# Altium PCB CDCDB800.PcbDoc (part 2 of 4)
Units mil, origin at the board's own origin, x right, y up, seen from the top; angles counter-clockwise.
Board outline 4100 x 4100 mil, 4 copper layers (Layer 1 - Top Layer, Layer 2 - GND, Layer 3 - PWR, Layer 4 - Bottom Layer), stack 61.2 mil thick; 245 components, 143 nets, 740 pads, 720 vias.
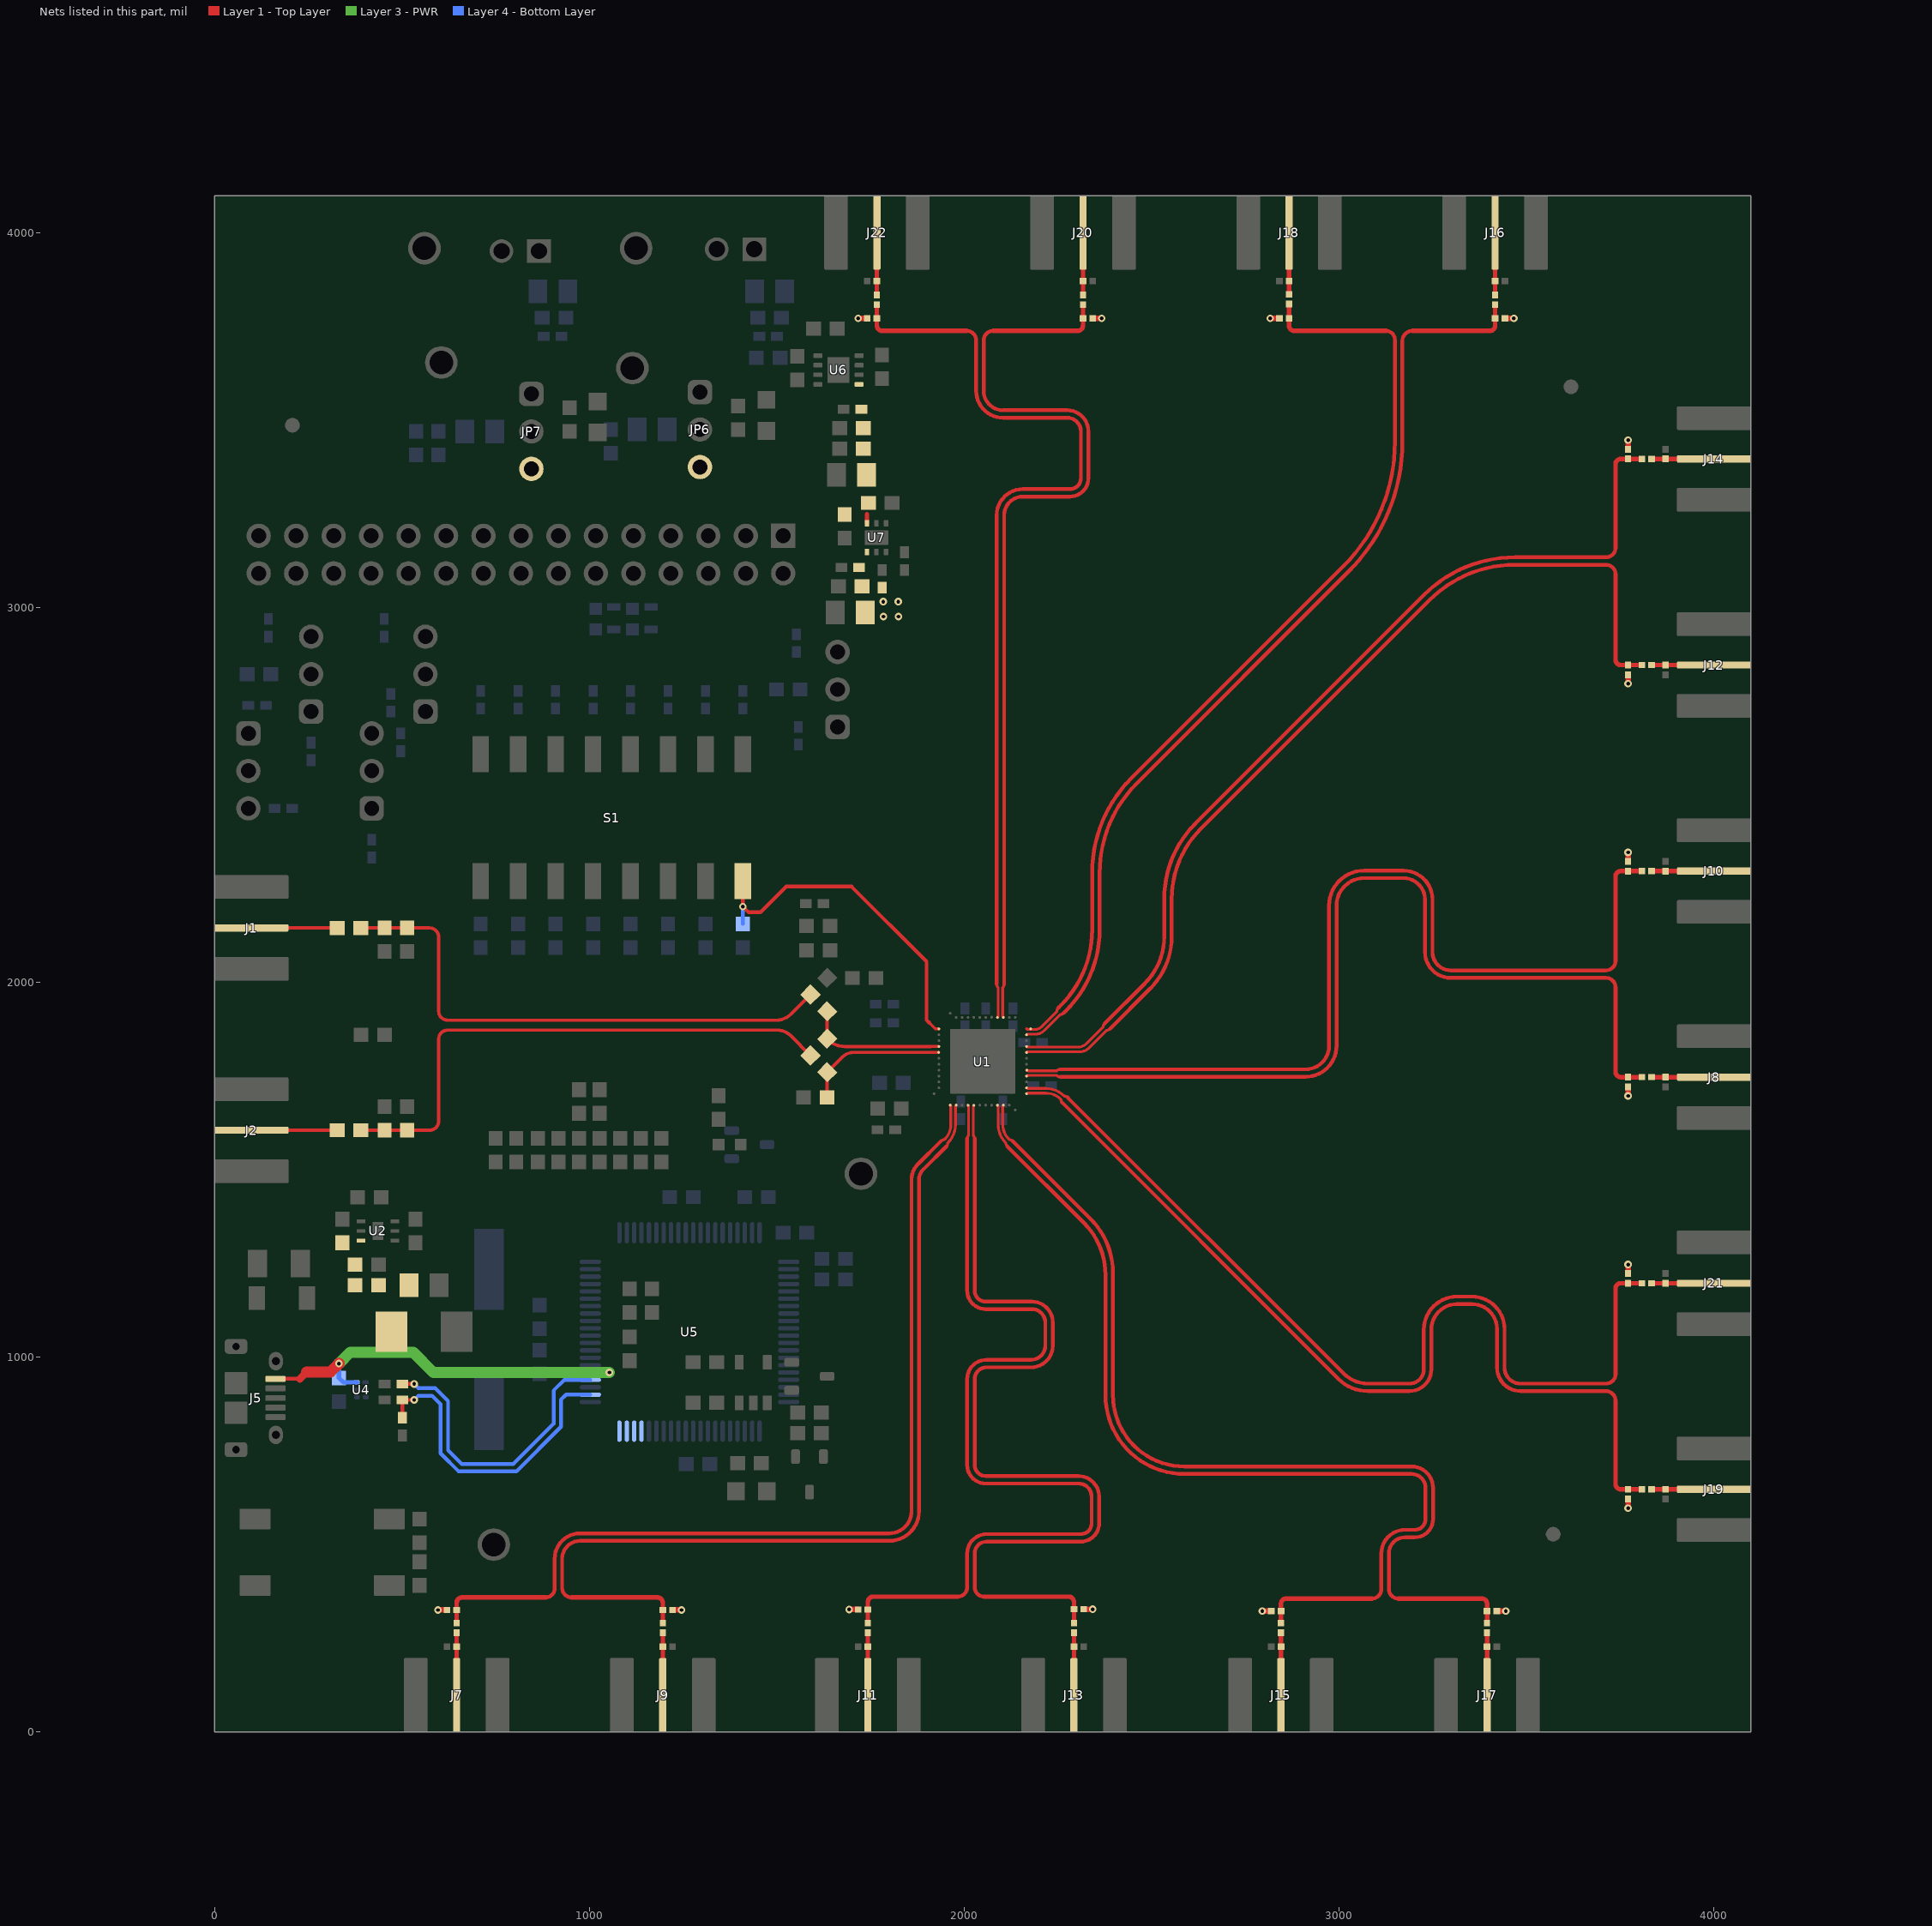
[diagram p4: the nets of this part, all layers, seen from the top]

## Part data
C1 C9 C36 C40 C44 C47: library part CMP-0086062-1, "CAP, CERM, 10 µF, 16 V,+/- 20%, X6S, 0603", Cap_Case=0603, Manufacturer=MuRata, TempCo=X6S, Tolerance_%=20%, Value2=16V, ValueDisplayed=10µF
C2 C3 C4 C5 C6 C7 C8 C10 C11 C12 C15 C37 C41 C45 C48: library part CMP-0006629-2, "CAP, CERM, 0.1 uF, 10 V, +/- 10%, X7R, 0402", Cap_Case=0402, Manufacturer=MuRata, Supplier Part Number 1=GRM155R71A104KA01D-ND, TempCo=X7R, Tolerance_%=10%, Value1=Unknown, Value2=10V, ValueDisplayed=0.1uF
C13 C14: library part CMP-0006722-4, "CAP, CERM, 33 pF, 100 V, +/- 5%, C0G/NP0, 0603", Cap_Case=0603, Manufacturer=AVX, Supplier Part Number 1=478-1143-1-ND, TempCo=C0G/NP0, Tolerance_%=5%, Value1="0.209 ohm", Value2=100V, ValueDisplayed=33pF
C16 C35 C39 C43 C46: library part CMP-0008403-2, "CAP, CERM, 22 uF, 10 V, +/- 20%, X5R, 0805", Cap_Case=0805, Manufacturer="Taiyo Yuden", Supplier Part Number 1=587-1958-1-ND, TempCo=X5R, Tolerance_%=20%, Value1=Unknown, Value2=10V, ValueDisplayed=22uF
C17 C18: library part CMP-0007003-5, "CAP, CERM, 10 uF, 10 V, +/- 20%, X5R, 0603", Cap_Case=0603, Manufacturer=TDK, Supplier Part Number 1=445-6853-1-ND, TempCo=X5R, Tolerance_%=20%, Value1="0.0078 ohm", Value2=10V, ValueDisplayed=10uF
C19 C20 C21 C30 C31 C32: library part CMP-0006857-4, "CAP, CERM, 0.1 uF, 16 V, +/- 5%, X7R, 0603", Cap_Case=0603, Manufacturer=Kemet, Supplier Part Number 1=399-1097-1-ND, TempCo=X7R, Tolerance_%=5%, Value1=Unknown, Value2=16V, ValueDisplayed=0.1uF
C22 C28: library part CMP-0006776-4, "CAP, CERM, 220 pF, 50 V, +/- 1%, C0G/NP0, 0603", Cap_Case=0603, Manufacturer=AVX, Supplier Part Number 1=478-3719-1-ND, TempCo=C0G/NP0, Tolerance_%=1%, Value1="0.083 ohm", Value2=50V, ValueDisplayed=220pF
C23: library part CMP-0006850-4, "CAP, CERM, 0.01 uF, 50 V, +/- 5%, X7R, 0603", Cap_Case=0603, Manufacturer=Kemet, Supplier Part Number 1=399-1092-1-ND, TempCo=X7R, Tolerance_%=5%, Value1=Unknown, Value2=50V, ValueDisplayed=0.01uF
C24: library part CMP-0082522-1, "CAP, CERM, 4.7 µF, 50 V,+/- 10%, X7R, 1206", Cap_Case=1206, Manufacturer=TDK, Supplier Part Number 1=445-172491-1-ND, TempCo=X7R, Tolerance_%=10%, Value2=50V, ValueDisplayed=4.7µF
C25 C26: library part CMP-0007261-4, "CAP, CERM, 30 pF, 100 V, +/- 5%, C0G/NP0, 0603", Cap_Case=0603, Manufacturer=MuRata, Supplier Part Number 1=490-1338-1-ND, TempCo=C0G/NP0, Tolerance_%=5%, Value1=Unknown, Value2=100V, ValueDisplayed=30pF
C27: library part CMP-0006898-4, "CAP, CERM, 2200 pF, 50 V, +/- 10%, X7R, 0603", Cap_Case=0603, Manufacturer=Kemet, Supplier Part Number 1=399-1085-1-ND, TempCo=X7R, Tolerance_%=10%, Value1=Unknown, Value2=50V, ValueDisplayed=2200pF
C29: library part CMP-0007373-4, "CAP, CERM, 0.47 uF, 10 V, +/- 10%, X7R, 0603", Cap_Case=0603, Manufacturer=MuRata, Supplier Part Number 1=GRM188R71A474KA61D-ND, TempCo=X7R, Tolerance_%=10%, Value1=Unknown, Value2=10V, ValueDisplayed=0.47uF
C33 C42: library part CMP-0007067-4, "CAP, CERM, 1 uF, 35 V, +/- 10%, X7R, AEC-Q200 Grade 1, 0603", Cap_Case=0603, Manufacturer=TDK, Supplier Part Number 1=445-174215-1-ND, TempCo=X7R, Tolerance_%=10%, Value1="0.005522 ohm", Value2=35V, ValueDisplayed=1uF
C34: library part CMP-0007497-5, "CAP, CERM, 10 uF, 10 V, +/- 20%, X7R, 0603", Cap_Case=0603, Manufacturer=MuRata, Supplier Part Number 1=81-GRM188Z71A106MA3D, TempCo=X7R, Tolerance_%=20%, Value1=Unknown, Value2=10V, ValueDisplayed=10uF
C38: library part CMP-0006814-5, "CAP, CERM, 0.01 uF, 10 V, +/- 10%, X7R, 0603", Cap_Case=0603, Manufacturer=AVX, Supplier Part Number 1=478-7938-2-ND, TempCo=X7R, Tolerance_%=10%, Value1=Unknown, Value2=10V, ValueDisplayed=0.01uF
D1: library part CMP-0005670-3, "Diode, Zener, 7.5 V, 550 mW, SMB", Manufacturer="ON Semiconductor", Power_W=550mW, Value1=0.55W
D2 D5 D6: library part CMP-0002829-3, "LED, Red, SMD", Color=red, Manufacturer=Lite-On, Value1=W, Value2=2V
D3: library part CMP-0028451-2, "Diode, Schottky, 30 V, 0.2 A, SOT-23", Manufacturer="Diodes Inc.", Value1=0.2A, Value2=0.65V
D4: library part CMP-0002827-3, "LED, Green, SMD", Color=green, Manufacturer=Lite-On, Power_TotalModule=100mW, Value1=0.1W, Value2=2.1V
FID1 FID2 FID3 FID4 FID5 FID6: library part CMP-0077181-1, "Fiducial mark.  There is nothing to buy or mount.", Manufacturer=N/A
H1 H2 H3 H4: library part CMP-0003620-1, "Bumpon, Hemisphere, 0.44 X 0.20, Clear", Manufacturer=3M, Supplier Part Number 1=SJ5303-7-ND
J1 J2 J7 J8 J9 J10 J11 J12 J13 J14 J15 J16 J17 J18 J19 J20 J21 J22: library part CMP-0088000-4, "CONN SMA JACK STR EDGE MNT", Manufacturer="RF Solutions Ltd."
J3 J4: library part CMP-0054974-1, "Terminal Block, 2x1, 2.54mm, TH", Manufacturer="TE Connectivity", Supplier Part Number 1=A98333-ND
J5: library part CMP-0074596-2, "Receptacle, USB 2.0, Micro-USB Type B, R/A, SMT", Color=Black, Current_A=1.8A, Manufacturer=FCI, Supplier Part Number 1=609-4618-1-ND, Voltage_V=100V
J6: library part CMP-0075468-1, "Header, 100mil, 15x2, Gold, TH", Manufacturer=Samtec
JP1 JP2 JP3 JP4 JP5 JP6 JP7: library part CMP-0075407-2, "Header, 100mil, 3x1, Gold, TH", Color=Black, Current_A=6.3A, Manufacturer=Samtec, Supplier Part Number 1=SAM1029-03-ND, Voltage_V=550V
L1 L2: library part CMP-0003081-1, "Ferrite Bead, 330 ohm @ 100 MHz, 2 A, 0805", Manufacturer="Wurth Elektronik", Supplier Part Number 1=732-1619-1-ND, Value1="0.08 ohm", Value2=2A, ValueDisplayed="330 ohm"
L3: library part CMP-0003426-2, "Ferrite Bead, 60 ohm @ 100 MHz, 3.5 A, 0603", Manufacturer=TDK, Supplier Part Number 1=445-1563-1-ND, Value1="0.02 ohm", Value2=3.5A, ValueDisplayed="60 ohm"
Q1: library part CMP-0000281-1, "MOSFET, N-CH, 25 V, 0.22 A, SOT-23", Alternate Manufacturer=None, Manufacturer="Fairchild Semiconductor", Supplier Part Number 1=FDV301NCT-ND, Value2="0.49 nC"
Q2: library part CMP-0000755-1, "MOSFET, N-CH, 50 V, 0.22 A, SOT-23", Alternate Manufacturer=None, Manufacturer="Fairchild Semiconductor", Supplier Part Number 1=BSS138CT-ND, Value2="1.7 nC"
R1: library part CMP-0022711-2, "RES, 2.20, 1%, 0.1 W, 0603", Manufacturer=Panasonic, Power_W=100mW, Supplier Part Number 1=P2.2AJCT-ND, TempCo="200 ppm/C", Tolerance_%=1%, Value2=0.1W, Value_Code=2R20, ValueDisplayed=2.20
R2 R3 R4 R5 R24 R25 R28 R29 R30 R33 R34 R36 R38 R40 R42 R44 R46 R48: library part CMP-0026740-1, "RES, 4.99 k, 1%, 0.063 W, 0402", Manufacturer="Yageo America", Power_W=63mW, Supplier Part Number 1=311-4.99KLRCT-ND, TempCo="100 ppm/C", Tolerance_%=1%, Value2=0.063W, Value_Code=4k99, ValueDisplayed=4.99k
R6 R14 R23 R26 R121 R122 R123: library part CMP-0025884-3, "RES, 0, 5%, 0.125 W, 0603", Manufacturer=Vishay/Beyschlag, Power_W=125mW, Supplier Part Number 1=MCT0603-0.0-ZZCT-ND, TempCo=ppm/C, Tolerance_%=5%, Value2=0.125W, Value_Code=0000, ValueDisplayed=0
R7 R9 R10 R11 R13 R15 R17 R18 R19: library part CMP-0025885-5, "RES, 0, 5%, 0.1 W, 0603", Manufacturer=Yageo, Power_W=100mW, Supplier Part Number 1=311-0.0GRCT-ND, TempCo="200 ppm/C", Tolerance_%=5%, Value2=0.1W, Value_Code=0000, ValueDisplayed=0
R8 R12 R16 R20: library part CMP-0021991-4, "RES, 100, 1%, 0.1 W, AEC-Q200 Grade 0, 0603", Manufacturer=Vishay-Dale, Power_W=100mW, Supplier Part Number 1=541-100HCT-ND, TempCo="100 ppm/C", Tolerance_%=1%, Value2=0.1W, Value_Code=100R, ValueDisplayed=100
R21 R22 R54 R58 R59 R60 R61 R64 R65 R66 R67 R69 R70: library part CMP-0025697-4, "RES, 0, 5%, 0.1 W, AEC-Q200 Grade 0, 0603", Manufacturer=Vishay-Dale, Power_W=100mW, Supplier Part Number 1=541-0.0GCT-ND, TempCo="200 ppm/C", Tolerance_%=5%, Value2=0.1W, Value_Code=0000, ValueDisplayed=0
R27 R31 R32 R35 R37 R39 R41 R43 R45 R47: library part CMP-0025758-4, "RES, 22, 5%, 0.1 W, AEC-Q200 Grade 0, 0603", Manufacturer=Vishay-Dale, Power_W=100mW, Supplier Part Number 1=541-22GCT-ND, TempCo="200 ppm/C", Tolerance_%=5%, Value2=0.1W, Value_Code=22R0, ValueDisplayed=22
R49 R72: library part CMP-0025786-4, "RES, 33 k, 5%, 0.1 W, AEC-Q200 Grade 0, 0603", Manufacturer=Vishay-Dale, Power_W=100mW, Supplier Part Number 1=541-33KGCT-ND, TempCo="200 ppm/C", Tolerance_%=5%, Value2=0.1W, Value_Code=33k0, ValueDisplayed=33k
R50 R52: library part CMP-0026908-3, "RES, 33, 5%, 0.063 W, AEC-Q200 Grade 0, 0402", Manufacturer=Vishay-Dale, Power_W=63mW, Supplier Part Number 1=541-33JCT-ND, TempCo="200 ppm/C", Tolerance_%=5%, Value2=0.063W, Value_Code=33R0, ValueDisplayed=33
R51 R126 R127: library part CMP-0025813-4, "RES, 470, 5%, 0.1 W, AEC-Q200 Grade 0, 0603", Manufacturer=Vishay-Dale, Power_W=100mW, Supplier Part Number 1=541-470GCT-ND, TempCo="200 ppm/C", Tolerance_%=5%, Value2=0.1W, Value_Code=470R, ValueDisplayed=470
R53: library part CMP-0026856-5, "RES, 1.5 k, 5%, 0.063 W, AEC-Q200 Grade 0, 0402", Manufacturer=Vishay-Dale, Power_W=63mW, Supplier Part Number 1=541-1.5KJCT-ND, TempCo="200 ppm/C", Tolerance_%=5%, Value2=0.063W, Value_Code=1k50, ValueDisplayed=1.5k
R55: library part CMP-0025738-4, "RES, 1.2 M, 5%, 0.1 W, AEC-Q200 Grade 0, 0603", Manufacturer=Vishay-Dale, Power_W=100mW, Supplier Part Number 1=541-1.2MGCT-ND, TempCo="200 ppm/C", Tolerance_%=5%, Value2=0.1W, Value_Code=1M20, ValueDisplayed=1.2M
R56: library part CMP-0025698-4, "RES, 100 k, 5%, 0.1 W, AEC-Q200 Grade 0, 0603", Manufacturer=Vishay-Dale, Power_W=100mW, Supplier Part Number 1=541-100KGCT-ND, TempCo="200 ppm/C", Tolerance_%=5%, Value2=0.1W, Value_Code=100k
R57: library part CMP-0017852-2, "RES, 110 k, 1%, 0.25 W, 1206", Manufacturer="Yageo America", Power_W=250mW, Supplier Part Number 1=311-110KFRCT-ND, TempCo="100 ppm/C", Tolerance_%=1%, Value2=0.25W, Value_Code=110k
R62 R63: library part CMP-0025944-5, "RES, 9.1 k, 5%, 0.1 W, 0603", Manufacturer=Yageo, Power_W=100mW, Supplier Part Number 1=311-9.1KGRCT-ND, TempCo="100 ppm/C", Tolerance_%=5%, Value2=0.1W, Value_Code=9k10, ValueDisplayed=9.1k
R68: library part CMP-0025700-4, "RES, 100, 5%, 0.1 W, AEC-Q200 Grade 0, 0603", Manufacturer=Vishay-Dale, Power_W=100mW, Supplier Part Number 1=541-100GCT-ND, TempCo="200 ppm/C", Tolerance_%=5%, Value2=0.1W, Value_Code=100R, ValueDisplayed=100
R71: library part CMP-0025823-4, "RES, 510, 5%, 0.1 W, AEC-Q200 Grade 0, 0603", Manufacturer=Vishay-Dale, Power_W=100mW, Supplier Part Number 1=541-510GCT-ND, TempCo="200 ppm/C", Tolerance_%=5%, Value2=0.1W, Value_Code=510R, ValueDisplayed=510
R73 R74 R79 R80 R85 R86 R91 R92 R97 R98 R103 R105 R109 R110 R115 R116: library part CMP-0027898-1, "RES, 84.5, 1%, 0.05 W, 0201", Manufacturer="Yageo America", Power_W=50mW, Supplier Part Number 1=YAG2822CT-ND, TempCo="200 ppm/C", Tolerance_%=1%, Value2=0.05W, Value_Code=84R5, ValueDisplayed=84.5
R75 R76 R83 R84 R87 R88 R95 R96 R99 R100 R107 R108 R111 R112 R119 R120: library part CMP-0027724-1, "RES, 47.5, 1%, 0.05 W, 0201", Manufacturer="Yageo America", Power_W=50mW, Supplier Part Number 1=YAG2693CT-ND, TempCo="200 ppm/C", Tolerance_%=1%, Value2=0.05W, Value_Code=47R5, ValueDisplayed=47.5
R77 R78 R81 R82 R89 R90 R93 R94 R101 R102 R104 R106 R113 R114 R117 R118: library part CMP-0027359-2, "RES, 147, 1%, 0.05 W, 0201", Manufacturer="Yageo America", Power_W=50mW, Supplier Part Number 1=YAG2410CT-ND, TempCo="200 ppm/C", Tolerance_%=1%, Value2=0.05W, Value_Code=147R, ValueDisplayed=147
R124: library part CMP-0026059-3, "RES, 18.2 k, 1%, 0.063 W, AEC-Q200 Grade 0, 0402", Manufacturer=Vishay-Dale, Power_W=63mW, Supplier Part Number 1=541-18.2KLCT-ND, TempCo="100 ppm/C", Tolerance_%=1%, Value2=0.063W, Value_Code=18k2, ValueDisplayed=18.2k
R125: library part CMP-0026403-2, "RES, 49.9 k, 1%, 0.063 W, AEC-Q200 Grade 0, 0402", Manufacturer=Vishay-Dale, Power_W=63mW, Supplier Part Number 1=541-49.9KLCT-ND, TempCo="100 ppm/C", Tolerance_%=1%, Value2=0.063W, Value_Code=49k9, ValueDisplayed=49.9k
S1: library part CMP-0002131-3, "Switch, Slide, SPST 8 poles, SMT", CurrentRating_mA=100A, Manufacturer="CTS Electrocomponents", Supplier Part Number 1=CT2198MST-ND
S2: library part CMP-0002134-3, "Switch, Tactile, SPST-NO, 0.05A, 12V, SMT", CurrentRating_mA=50A, Manufacturer="TE Connectivity", Supplier Part Number 1=450-1129-ND
SH1 SH2 SH3 SH4: library part CMP-0003623-3, "Shunt, 100mil, Gold plated, Black", Alternate Manufacturer=3M, Alternate PartNumber=969102-0000-DA, Manufacturer=Samtec, Supplier Part Number 1=SAM8858-ND
TP1 TP2 TP3 TP5: library part CMP-0055147-1, "Test Point, Multipurpose, Red, TH", Color=Red, Manufacturer=Keystone, Supplier Part Number 1=36-5010-ND
TP4 TP6: library part CMP-0055148-1, "Test Point, Multipurpose, Black, TH", Color=Black, Manufacturer=Keystone, Supplier Part Number 1=36-5011-ND
U1: library part CMP-0091223-1, "8-output LP-HCSL clock buffer capable of distributing the reference clocks for PCIe Gen 1-5, QPI, UPI, SAS, and SATA interfaces", Manufacturer="Texas Instruments", Max Supply Voltage=3.63V, Min Supply Voltage=2.97V, Nominal Supply Current=5-63mA, Operating Temperature Range="-40°C to +105°C"
U2: library part CMP-0066010-1, "150-mA Ultra-Low Noise LDO for RF and Analog Circuits Requires No Bypass Capacitor, NGF0006A (WSON-6)", Alternate Manufacturer="Texas Instruments"
U3: library part CMP-0052046-2, "Single 2-Input Exclusive-OR Gate, DBV0005A (SOT-23-5)", F @ Nom Voltage(Max)(Mhz)=150, Generic Part Number=SN74LVC1G86, ICC @ Nom Voltage(Max)(mA)=0.01, Manufacturer="Texas Instruments", Operating Temperature Range="-40 to 125 C", Rating=Catalog, tpd @ Nom Voltage(Max)(ns)=9.9,5.5,5,4, Voltage(Nom)(V)=1.8,2.5,3.3,5
U4: library part CMP-0043115-3, "4-Channel ESD Protection Array for High-Speed Data Interfaces, DRY0006A (USON-6)", Breakdown Voltage(Min)(V)=6, IO Capacitance(Typ)(pF)=1.6, IO Leakage Current(nA)=1, Manufacturer="Texas Instruments", Operating Temperature Range="-40 to 85 C", Rating=Catalog
U5: library part CMP-0038965-1, "25 MHz Mixed Signal Microcontroller with 128 KB Flash, 8192 B SRAM and 63 GPIOs, -40 to 85 degC, 80-pin QFP (PN), Green (RoHS & no Sb/Br)", Frequency(MHz)=25, Manufacturer="Texas Instruments", Temp Sensor=Yes
U6: library part CMP-0036329-3, "500mA, Adjustable, Low Quiescent Current, Low-Noise, High-PSRR, Single-Output LDO Regulator, DRB0008A (VSON-8)", Manufacturer="Texas Instruments", Operating Temperature Range="-40 to 125 C", Rating=Catalog
U7: library part CMP-0082614-1, "500-mA LDO With Power-Good, DRV0006A (WSON-6)", Alternate Manufacturer="Texas Instruments", Alternate PartNumber=TPS74501PDRVT, Operating Temperature Range="-40 to 125 C"
Y1: library part CMP-0004572-3, "Crystal, 24.000 MHz, 20pF, SMD", Frequency_Fixed=24MHz, Frequency Stability=+/-50ppm, Manufacturer="ECS Inc.", Supplier Part Number 1=XC1255CT-ND

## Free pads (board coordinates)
  rrect50% 55.28x29.68 on Bottom Solder: ""(57.09,753.42) ""(57.09,1029.02)

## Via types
v1: diameter 22, hole 10, Layer 1 - Top Layer to Layer 4 - Bottom Layer, tented top, 430 vias
v2: diameter 20, hole 10, Layer 1 - Top Layer to Layer 4 - Bottom Layer, tented top, 268 vias
v3: diameter 19.68, hole 7.87, Layer 1 - Top Layer to Layer 4 - Bottom Layer, 22 vias

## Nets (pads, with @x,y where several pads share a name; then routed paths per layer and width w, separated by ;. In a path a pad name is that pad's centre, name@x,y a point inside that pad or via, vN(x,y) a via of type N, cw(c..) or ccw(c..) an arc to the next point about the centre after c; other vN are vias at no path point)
0V75: C43.1 C44.1 C45.1 R73.2 R74.2 R79.2 R80.2 R85.2 R86.2 R91.2 R92.2 R97.2 R98.2 R103.2 R105.2 R109.2 R110.2 R115.2 R116.2 R124.2 U7.1 | length 384.9
  Layer 1 - Top Layer w15: v2(596,325.59) R73.2@620.05,325.59 ; R79.2@1222.02,325.59 v2(1246.08,325.59) ; v2(1693.46,326.89) R85.2@1717.52,326.89 ; v2(1717.55,3772.9) R116.2@1741.61,3772.9 ; R91.2@2319.49,327.59 v2(2343.54,327.59) ; R110.2@2343.58,3772.9 v2(2367.64,3772.9) ; v2(2796,322.6) R97.2@2820.05,322.6 ; v2(2817.56,3772.9) R105.2@2841.61,3772.9 ; R103.2@3422.02,322.6 v2(3446.08,322.6) ; R98.2@3443.58,3772.9 v2(3467.64,3772.9) ; v2(3772.4,597.56) R109.2@3772.4,621.61 ; R115.2@3772.4,1223.58 v2(3772.4,1247.64) ; v2(3772.4,1697.56) R74.2@3772.4,1721.61 ; R80.2@3772.4,2323.58 v2(3772.4,2347.64) ; v2(3772.4,2797.56) R86.2@3772.4,2821.61 ; R92.2@3772.4,3423.58 v2(3772.4,3447.64)
  other v2: 1785,2976.9 1825,2976.9 1784.6,3016.7 1824.6,3016.7
3V3_INT: C34.1 C35.1 C36.1 C37.1 C42.1 JP6.3 JP7.3 R123.1 U6.1 U7.6 | length 25.2
  Layer 1 - Top Layer w11: U7.6@1740.91,3226 1740.91,3251.2
5V_USB: C16.1 C21.2 D1.1 J5.1 L3.1 U4.6 U5.65 | length 1085.5
  Layer 1 - Top Layer w10.1: J5.1@162.4,942.4 227.4,942.4
  Layer 1 - Top Layer w20: 227.4,942.4 245.6,960.6
  Layer 1 - Top Layer w30: 245.6,960.6 309.15,960.6 v2(331.78,983.22)
  Layer 3 - PWR w30: v2(331.78,983.22) 362.15,1013.6 529.9,1013.6 584.17,959.33 v2(1053.5,959.33)
  Layer 4 - Bottom Layer w10.1: U5.65@1002.64,959.33 v2(1053.5,959.33)
  Layer 4 - Bottom Layer w11.81: v2(331.78,983.22) C21.2@331.78,944.79 343.59,932.98 U4.6@379.97,932.98
5V_USB_FILT: C17.1 L3.2 R49.2 U2.6
CK0_N: R79.1 R83.1 U1.14 | length 2567.4
  Layer 1 - Top Layer w7.5: 1953.25,1563.26 ccw(c1944.2,1572.31) 1957,1572.31 ccw(c1907.48,1621.83) 1977.51,1621.83 1977.51,1668.95 cw(c1983.05,1668.95) U1.14@1979.13,1672.87
  Layer 1 - Top Layer w10: 952.94,358.99 cw(c952.94,384.39) 927.54,384.39 927.54,462.25 cw(c975.29,462.25) 975.29,510 1800.6,510 ccw(c1800.6,589.4) 1880,589.4 1880,1474.6 cw(c1917.21,1474.6) 1890.9,1500.91 1953.25,1563.26
  Layer 1 - Top Layer w12: 952.94,358.99 1181.94,358.99 cw(c1181.94,344.9) 1196.04,344.9 R79.1@1196.04,325.59 R83.1@1196.04,290.59
CK0_P: R73.1 R75.1 U1.13 | length 2566.8
  Layer 1 - Top Layer w7.5: 1939.11,1577.41 cw(c1948.16,1568.35) 1948.16,1581.15 ccw(c1907.48,1621.83) 1965.01,1621.83 1965.01,1668.95 ccw(c1959.46,1668.95) U1.13@1963.39,1672.87
  Layer 1 - Top Layer w10: 883.44,358.99 ccw(c883.44,383.09) 907.54,383.09 907.54,462.25 cw(c975.29,462.25) 975.29,530 1800.6,530 ccw(c1800.6,589.4) 1860,589.4 1860,1474.6 cw(c1917.21,1474.6) 1876.76,1515.05 1939.11,1577.41
  Layer 1 - Top Layer w12: R75.1@646.04,290.59 R73.1@646.04,325.59 646.04,344.9 cw(c660.13,344.9) 660.13,358.99 883.44,358.99
CK0_SMA_N: J9.1 R81.1 R83.2 | length 166.2
  Layer 1 - Top Layer w12: J9.1@1196.04,98.43 R81.1@1196.04,227.6 R83.2@1196.04,264.61
CK0_SMA_P: J7.1 R75.2 R77.2 | length 166.2
  Layer 1 - Top Layer w12: J7.1@646.04,98.43 R77.2@646.04,227.6 R75.2@646.04,264.61
CK1_N: R91.1 R95.1 U1.17 | length 2567
  Layer 1 - Top Layer w7.5: U1.17@2026.38,1672.46 ccw(c2030.3,1668.54) 2024.75,1668.54 2024.75,1592.42 cw(c2015.7,1583.37) 2028.5,1583.37
  Layer 1 - Top Layer w10: 2028.5,1583.37 2028.5,1177.8 ccw(c2057.7,1177.8) 2057.7,1148.6 2181.3,1148.6 cw(c2181.3,1092.9) 2237,1092.9 2237,1030.99 cw(c2179.31,1030.99) 2179.31,973.3 2060.09,973.3 ccw(c2060.09,941.72) 2028.5,941.72 2028.5,712.4 ccw(c2057.7,712.4) 2057.7,683.2 2305.1,683.2 cw(c2305.1,627.5) 2360.8,627.5 2360.8,557.28 cw(c2311.42,557.28) 2311.42,507.9 2060.09,507.9 ccw(c2060.09,476.32) 2028.5,476.32 2028.5,386.39 ccw(c2053.9,386.39) 2053.9,360.99
  Layer 1 - Top Layer w12: 2053.9,360.99 2279.41,360.99 cw(c2279.41,346.9) 2293.5,346.9 R91.1@2293.5,327.59 R95.1@2293.5,290.59
CK1_P: R85.1 R87.1 U1.16 | length 2566.3
  Layer 1 - Top Layer w7.5: 2008.5,1583.37 cw(c2021.31,1583.37) 2012.25,1592.42 2012.25,1668.54 ccw(c2006.71,1668.54) U1.16@2010.63,1672.46
  Layer 1 - Top Layer w10: 1983.1,360.99 ccw(c1983.1,386.39) 2008.5,386.39 2008.5,437.52 2008.5,476.32 cw(c2060.09,476.32) 2060.09,527.9 2311.42,527.9 ccw(c2311.42,557.28) 2340.8,557.28 2340.8,627.5 ccw(c2305.1,627.5) 2305.1,663.2 2057.7,663.2 cw(c2057.7,712.4) 2008.5,712.4 2008.5,941.72 cw(c2060.09,941.72) 2060.09,993.3 2179.31,993.3 ccw(c2179.31,1030.99) 2217,1030.99 2217,1092.9 ccw(c2181.3,1092.9) 2181.3,1128.6 2057.7,1128.6 cw(c2057.7,1177.8) 2008.5,1177.8 2008.5,1583.37
  Layer 1 - Top Layer w12: R87.1@1743.5,290.59 R85.1@1743.5,326.89 ; R85.1@1743.5,327.59 1743.5,346.9 cw(c1757.6,346.9) 1757.6,360.99 1983.1,360.99
CK1_SMA_N: J13.1 R93.1 R95.2 | length 166.2
  Layer 1 - Top Layer w12: J13.1@2293.5,98.43 R93.1@2293.5,227.6 R95.2@2293.5,264.61
CK1_SMA_P: J11.1 R87.2 R89.2 | length 166.2
  Layer 1 - Top Layer w12: J11.1@1743.5,98.42 R89.2@1743.5,227.6 R87.2@1743.5,264.61
CK2_N: R103.1 R107.1 U1.22 | length 2566.9
  Layer 1 - Top Layer w7.5: U1.22@2105.12,1672.87 ccw(c2109.04,1668.95) 2103.49,1668.95 2103.49,1621.83 ccw(c2161.02,1621.83) 2120.34,1581.15 cw(c2120.34,1568.35) 2129.4,1577.41
  Layer 1 - Top Layer w10: 2129.4,1577.41 2152.91,1553.89 2337.85,1368.95 ; 2337.9,1368.9 cw(c2193.6,1224.7) 2397.6,1224.7 2397.6,899.13 ccw(c2588.23,899.13) 2588.23,708.5 3194.87,708.5 cw(c3194.87,651.57) 3251.8,651.57 3251.8,567.89 cw(c3203.31,567.89) 3203.31,519.4 ; 3159.44,356 cw(c3159.44,381.4) 3134.04,381.4 3134.04,476.58 cw(c3176.85,476.58) 3176.85,519.4 3202.9,519.4
  Layer 1 - Top Layer w12: 3159.44,356 3381.94,356 cw(c3381.94,341.91) 3396.04,341.91 R103.1@3396.04,322.6 R107.1@3396.04,290.59
CK2_P: R97.1 R99.1 U1.21 | length 2567
  Layer 1 - Top Layer w7.5: U1.21@2089.37,1672.87 cw(c2085.45,1668.95) 2090.99,1668.95 2090.99,1621.83 ccw(c2161.02,1621.83) 2111.51,1572.32 ccw(c2124.31,1572.31) 2115.25,1563.26
  Layer 1 - Top Layer w10: 2115.25,1563.26 2320.41,1358.11 cw(c2182.33,1220.03) 2377.6,1220.03 2377.6,899.13 ccw(c2588.23,899.13) 2588.23,688.5 3194.87,688.5 cw(c3194.87,651.57) 3231.8,651.57 3231.8,567.89 cw(c3203.31,567.89) 3203.31,539.4 3176.85,539.4 ccw(c3176.85,476.58) 3114.04,476.58 3114.04,381.4 cw(c3088.64,381.4) 3088.64,356
  Layer 1 - Top Layer w12: R99.1@2846.04,290.59 R97.1@2846.04,322.6 2846.04,341.91 cw(c2860.13,341.91) 2860.13,356 3088.64,356
CK2_SMA_N: J17.1 R104.1 R107.2 | length 166.2
  Layer 1 - Top Layer w12: J17.1@3396.04,98.43 R104.1@3396.04,227.6 R107.2@3396.04,264.61
CK2_SMA_P: J15.1 R99.2 R101.2 | length 166.2
  Layer 1 - Top Layer w12: J15.1@2846.04,98.43 R101.2@2846.04,227.6 R99.2@2846.04,264.61
CK3_N: R115.1 R119.1 U1.26 | length 2566.6
  Layer 1 - Top Layer w7.5: U1.26@2167.13,1719.13 ccw(c2171.05,1723.05) 2171.05,1717.51 2218.17,1717.51 cw(c2218.17,1647.48) 2267.68,1697 cw(c2267.68,1684.2) 2276.74,1693.25
  Layer 1 - Top Layer w10: 2276.74,1693.25 3012.89,957.09 ; 3013.22,956.77 ccw(c3078.81,1022.36) 3078.81,929.6 3188.91,929.6 ccw(c3188.91,967.99) 3227.3,967.99 3227.3,1073.5 cw(c3315.7,1073.5) 3315.7,1161.9 3355.77,1161.9 cw(c3355.77,1074.97) 3442.7,1074.97 3442.7,972.45 ccw(c3485.55,972.45) 3485.55,929.6 3713.6,929.6 ccw(c3713.6,955) 3739,955
  Layer 1 - Top Layer w12: 3739,955 3739,1183.5 cw(c3753.09,1183.5) 3753.09,1197.6 R115.1@3772.4,1197.6 R119.1@3809.41,1197.6
CK3_P: R109.1 R111.1 U1.25 | length 2567.1
  Layer 1 - Top Layer w7.5: U1.25@2167.13,1703.39 cw(c2171.05,1699.46) 2171.05,1705.01 2218.17,1705.01 cw(c2218.17,1647.48) 2258.85,1688.16 ccw(c2271.65,1688.16) 2262.59,1679.11
  Layer 1 - Top Layer w10: 2262.59,1679.11 2999.82,941.89 ccw(c3077.77,1019.84) 3077.77,909.6 3188.91,909.6 ccw(c3188.91,967.99) 3247.3,967.99 3247.3,1073.5 cw(c3315.7,1073.5) 3315.7,1141.9 3355.77,1141.9 cw(c3355.77,1074.97) 3422.7,1074.97 3422.7,972.45 ccw(c3485.55,972.45) 3485.55,909.6 3713.6,909.6 cw(c3713.6,884.2) 3739,884.2
  Layer 1 - Top Layer w12: 3739,884.2 3739,661.69 ccw(c3753.09,661.69) 3753.09,647.6 R109.1@3772.4,647.6 R111.1@3809.41,647.6
CK3_SMA_N: J21.1 R117.1 R119.2 | length 166.2
  Layer 1 - Top Layer w12: R119.2@3835.39,1197.6 R117.1@3872.4,1197.6 J21.1@4001.57,1197.6
CK3_SMA_P: J19.1 R111.2 R113.2 | length 166.2
  Layer 1 - Top Layer w12: R111.2@3835.39,647.6 R113.2@3872.4,647.6 J19.1@4001.57,647.6
CK4_N: R80.1 R84.1 U1.29 | length 2566.8
  Layer 1 - Top Layer w7.5: U1.29@2167.54,1766.38 ccw(c2171.46,1770.3) 2171.46,1764.75 2247.58,1764.75 cw(c2256.63,1755.7) 2256.63,1768.5
  Layer 1 - Top Layer w10: 2256.63,1768.5 2911.6,1768.5 ccw(c2911.6,1831.2) 2974.3,1831.2 2974.3,2205.6 cw(c3067.5,2205.6) 3067.5,2298.8 3173.1,2298.8 cw(c3173.1,2221.5) 3250.4,2221.5 3250.4,2081.4 ccw(c3299.2,2081.4) 3299.2,2032.6 3713.6,2032.6 ccw(c3713.6,2058) 3739,2058
  Layer 1 - Top Layer w12: 3739,2058 3739,2283.5 cw(c3753.09,2283.5) 3753.09,2297.6 R80.1@3772.4,2297.6 R84.1@3809.41,2297.6
CK4_P: R74.1 R76.1 U1.28 | length 2566.8
  Layer 1 - Top Layer w7.5: U1.28@2167.54,1750.63 cw(c2171.46,1746.71) 2171.46,1752.25 2247.58,1752.25 ccw(c2256.63,1761.31) 2256.63,1748.5
  Layer 1 - Top Layer w10: 2256.63,1748.5 2911.6,1748.5 ccw(c2911.6,1831.2) 2994.3,1831.2 2994.3,2205.6 cw(c3067.5,2205.6) 3067.5,2278.8 3173.1,2278.8 cw(c3173.1,2221.5) 3230.4,2221.5 3230.4,2081.4 ccw(c3299.2,2081.4) 3299.2,2012.6 3713.6,2012.6 cw(c3713.6,1987.2) 3739,1987.2
  Layer 1 - Top Layer w12: 3739,1987.2 3739,1761.69 ccw(c3753.09,1761.69) 3753.09,1747.6 R74.1@3772.4,1747.6 R76.1@3809.41,1747.6
CK4_SMA_N: J10.1 R82.1 R84.2 | length 166.2
  Layer 1 - Top Layer w12: R84.2@3835.39,2297.6 R82.1@3872.4,2297.6 J10.1@4001.57,2297.6
CK4_SMA_P: J8.1 R76.2 R78.2 | length 166.2
  Layer 1 - Top Layer w12: R76.2@3835.39,1747.6 R78.2@3872.4,1747.6 J8.1@4001.57,1747.6
CK5_N: R92.1 R96.1 U1.33 | length 2567
  Layer 1 - Top Layer w7.5: U1.33@2167.13,1829.37 ccw(c2171.05,1833.29) 2171.05,1827.75 2303.67,1827.75 ccw(c2303.67,1861.73) 2327.68,1837.68 2367.75,1877.75 2371.25,1881.25 cw(c2384.06,1881.25) 2375,1890.3
  Layer 1 - Top Layer w10: 2375,1890.3 2482.87,1998.18 ccw(c2358.23,2122.82) 2534.5,2122.82 2534.5,2223.46 cw(c2819.19,2223.46) 2617.88,2424.77 3227.68,3034.56 ; 3227.71,3034.6 cw(c3470.64,2791.6) 3470.64,3135.2 3713.6,3135.2 ccw(c3713.6,3160.6) 3739,3160.6
  Layer 1 - Top Layer w12: 3739,3160.6 3739,3383.5 cw(c3753.09,3383.5) 3753.09,3397.6 R92.1@3772.4,3397.6 R96.1@3809.41,3397.6
CK5_P: R86.1 R88.1 U1.32 | length 2566.9
  Layer 1 - Top Layer w7.5: U1.32@2167.13,1813.62 cw(c2171.05,1809.7) 2171.05,1815.25 2308.85,1815.25 ccw(c2308.85,1849.23) 2332.88,1825.2 2380.09,1872.41 ccw(c2380.09,1885.22) 2389.14,1876.16
  Layer 1 - Top Layer w10: 2389.14,1876.16 2497.01,1984.03 ccw(c2358.23,2122.82) 2554.5,2122.82 2554.5,2223.46 cw(c2819.19,2223.46) 2632.02,2410.62 3241.82,3020.42 cw(c3470.63,2791.6) 3470.63,3115.2 3713.6,3115.2 cw(c3713.6,3089.8) 3739,3089.8
  Layer 1 - Top Layer w12: 3739,3089.8 3739,2861.69 ccw(c3753.09,2861.69) 3753.09,2847.6 R86.1@3772.4,2847.6 R88.1@3809.41,2847.6
CK5_SMA_N: J14.1 R94.1 R96.2 | length 166.2
  Layer 1 - Top Layer w12: R96.2@3835.39,3397.6 R94.1@3872.4,3397.6 J14.1@4001.57,3397.6
CK5_SMA_P: J12.1 R88.2 R90.2 | length 166.2
  Layer 1 - Top Layer w12: R88.2@3835.39,2847.6 R90.2@3872.4,2847.6 J12.1@4001.57,2847.6
CK6_N: R105.1 R108.1 U1.36 | length 2579.3
  Layer 1 - Top Layer w7.5: 2167.13,1876.61 ccw(c2171.05,1880.54) 2171.05,1874.99 2191.61,1874.99 ccw(c2191.61,1893.81) 2204.92,1880.5 2248.04,1923.62 cw(c2260.84,1923.62) 2251.79,1932.67
  Layer 1 - Top Layer w10: 2251.79,1932.67 2258.28,1939.16 ccw(c2055.91,2141.53) 2342.1,2141.53 2342.1,2292.54 cw(c2700.48,2292.54) 2447.07,2545.95 3012.77,3111.66 ccw(c2681.25,3443.18) 3150.1,3443.18 3150.1,3715.48 ccw(c3126.07,3715.48) 3126.07,3739.5
  Layer 1 - Top Layer w12: R108.1@2867.6,3810.82 R105.1@2867.6,3772.9 2867.6,3753.6 ccw(c2881.69,3753.6) 2881.6,3739.5 ; 3126.07,3739.5 2881.69,3739.5 ; 2881.6,3739.5 ccw(c2881.69,3753.6) 2881.69,3739.5 ; 2881.6,3739.5 2881.69,3739.5
CK6_P: R98.1 R100.1 U1.35 | length 2567.2
  Layer 1 - Top Layer w7.5: U1.35@2167.13,1860.87 cw(c2171.05,1856.95) 2171.05,1862.49 2191.61,1862.49 ccw(c2191.61,1893.81) 2213.76,1871.66 2256.88,1914.78 ccw(c2256.88,1927.59) 2265.93,1918.53
  Layer 1 - Top Layer w10: 2265.93,1918.53 2272.42,1925.02 ccw(c2055.91,2141.53) 2362.1,2141.53 2362.1,2292.54 cw(c2700.48,2292.54) 2461.21,2531.81 3026.92,3097.52 ccw(c2681.25,3443.19) 3170.1,3443.19 3170.1,3712.86 cw(c3196.74,3712.86) 3196.74,3739.5
  Layer 1 - Top Layer w12: 3196.74,3739.5 3403.5,3739.5 ccw(c3403.5,3753.6) 3417.6,3753.6 R98.1@3417.6,3772.9 R100.1@3417.6,3809.41
CK6_SMA_N: J18.1 R106.1 R108.2 | length 164.8
  Layer 1 - Top Layer w12: R108.2@2867.6,3836.81 R106.1@2867.6,3872.4 J18.1@2867.6,4001.57
CK6_SMA_P: J16.1 R100.2 R102.2 | length 166.2
  Layer 1 - Top Layer w12: R100.2@3417.6,3835.39 R102.2@3417.6,3872.4 J16.1@3417.6,4001.57
CK7_N: R116.1 R120.1 U1.40 | length 2567.1
  Layer 1 - Top Layer w7.5: 2087.24,1996.22 ccw(c2100.05,1996.22) 2090.99,1987.17 2090.99,1911.05 cw(c2085.45,1911.05) U1.40@2089.37,1907.13
  Layer 1 - Top Layer w10: 2007.2,3739.5 cw(c2007.2,3714.1) 2032.6,3714.1 2032.6,3579.2 ccw(c2104.3,3579.2) 2104.3,3507.5 2275.5,3507.5 cw(c2275.5,3470.9) 2312.1,3470.9 2312.1,3346.5 cw(c2282.7,3346.5) 2282.7,3317.1 2157.04,3317.1 ccw(c2157.04,3247.3) 2087.24,3247.3 2087.24,2032.2 2087.24,1996.22
  Layer 1 - Top Layer w12: R120.1@1767.6,3809.41 R116.1@1767.6,3772.9 1767.6,3753.6 ccw(c1781.69,3753.6) 1781.69,3739.5 2007.2,3739.5
CK7_P: R110.1 R112.1 U1.39 | length 2567.1
  Layer 1 - Top Layer w7.5: U1.39@2105.12,1907.13 cw(c2109.04,1911.05) 2103.49,1911.05 2103.49,1987.17 ccw(c2094.44,1996.22) 2107.24,1996.22
  Layer 1 - Top Layer w10: 2078,3739.5 ccw(c2078,3714.1) 2052.6,3714.1 2052.6,3579.2 ccw(c2104.3,3579.2) 2104.3,3527.5 2275.5,3527.5 cw(c2275.5,3470.9) 2332.1,3470.9 2332.1,3346.5 cw(c2282.7,3346.5) 2282.7,3297.1 2157.04,3297.1 ccw(c2157.04,3247.3) 2107.24,3247.3 2107.24,2032.2 2107.24,1996.22
  Layer 1 - Top Layer w12: 2078,3739.5 2303.5,3739.5 ccw(c2303.5,3753.6) 2317.6,3753.6 R110.1@2317.6,3772.9 R112.1@2317.6,3809.41
CK7_SMA_N: J22.1 R118.1 R120.2 | length 166.2
  Layer 1 - Top Layer w12: R120.2@1767.6,3835.39 R118.1@1767.6,3872.4 J22.1@1767.6,4001.57
CK7_SMA_P: J20.1 R112.2 R114.2 | length 166.2
  Layer 1 - Top Layer w12: R112.2@2317.6,3835.39 R114.2@2317.6,3872.4 J20.1@2317.6,4001.57
CKPWRGD_PD#: R47.2 S1.8 U1.1 | length 920.6
  Layer 1 - Top Layer w7.87: 1907.65,1892.35 1923.39,1876.61 U1.1@1932.87,1876.61
  Layer 1 - Top Layer w10.1: S1.8@1410,2270.71 v2(1410,2202.68) 1425.18,2187.5 1456.4,2187.5 1525.1,2256.2 1700,2256.2 1900,2056.2 1900,1900 1907.65,1892.35
  Layer 4 - Bottom Layer w10.1: R47.2@1410,2156.5 v2(1410,2202.68)
CLKIN_N: R15.1 R16.2 R18.2 R19.1 R20.1 | length 1472.9
  Layer 1 - Top Layer w8.8: R18.2@390,1605.85 R20.1@513.5,1605.85 573.2,1605.85 ccw(c573.2,1630.65) 598,1630.65 598,1849.39 cw(c621.9,1849.39) 621.9,1873.3 1501.41,1873.3 ; 1501.43,1873.3 cw(c1501.41,1822.93) 1537.03,1858.54 R19.1@1590.33,1805.25
CLKIN_N1: R11.2 R15.2 U1.4 | length 377
  Layer 1 - Top Layer w7.87: 1910.3,1829.37 U1.4@1932.87,1829.37
  Layer 1 - Top Layer w8.8: R11.2@1634.87,1923.2 R15.2@1634.87,1849.79 1636.05,1848.61 ccw(c1682.5,1895.06) 1682.5,1829.37 1910.3,1829.37
CLKIN_N2: R17.2 R19.2 U1.5 | length 384.6
  Layer 1 - Top Layer w7.87: 1909.89,1813.62 U1.5@1932.46,1813.62
  Layer 1 - Top Layer w8.8: R17.2@1634.87,1693.77 R19.2@1634.87,1760.7 1675.48,1801.31 ; 1675.49,1801.32 cw(c1705.2,1771.59) 1705.2,1813.62 1909.89,1813.62
CLKIN_P: R8.2 R9.1 R10.2 R11.1 R12.1 | length 1451.3
  Layer 1 - Top Layer w8.8: R10.2@390,2145.85 R8.2@513.5,2145.85 573.2,2145.85 cw(c573.2,2121.05) 598,2121.05 598,1923.6 ccw(c621.9,1923.6) 621.9,1899.7 1498.78,1899.7 ccw(c1498.78,1956.42) 1538.86,1916.28 R9.1@1590.33,1967.75
CLKIN_SMA_N: J2.1 R18.1 | length 227.7
  Layer 1 - Top Layer w8.8: J2.1@99.33,1605.85 R18.1@327.01,1605.85
CLKIN_SMA_P: J1.1 R10.1 | length 227.7
  Layer 1 - Top Layer w8.8: J1.1@99.33,2145.85 R10.1@327.01,2145.85
D_N: R50.2 U5.64 | length 811.4
  Layer 1 - Top Layer w10.1: R50.2@500.92,928.7 v2(532.73,928.7)
  Layer 4 - Bottom Layer w10.1: v2(532.73,928.7) 543.93,917.5 588.73,917.5 623.1,883.13 623.1,752 659.7,715.4 797.1,715.4 904.7,823 904.7,911.2 933.15,939.65 U5.64@1002.64,939.65
D_P: R52.2 R53.2 U5.62 | length 842
  Layer 1 - Top Layer w10.1: R53.2@500.92,838.47 R52.2@500.92,886.27 v2(532.73,886.27)
  Layer 4 - Bottom Layer w10.1: v2(532.73,886.27) 543.86,897.4 580.4,897.4 603,874.8 603,743.67 651.37,695.3 805.43,695.3 924.8,814.67 924.8,887.1 937.98,900.28 U5.62@1002.64,900.28
EXT3V3_EN: U5.59
EXT3V3_FAULT: U5.60
EXT5V_EN: U5.57
EXT5V_FAULT: U5.58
